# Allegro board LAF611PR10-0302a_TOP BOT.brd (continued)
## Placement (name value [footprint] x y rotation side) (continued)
CV212  0.1U_0201_6.3V6K  [C_0201]  207.16 91.02 90 bottom
CV213  4.7U_0603_6.3V6K  [C_0603]  232.72 100.22 0 top
CV214  1U_0402_6.3V6K  [C_0402]  226.76 100.01 270 top
CV373  10U_0603_6.3V6M  [C_0603]  223 149.51 90 top
CV374  1U_0402_6.3V6K  [C_0402]  235.13 144.44 270 top
CV375  1U_0402_6.3V6K  [C_0402]  237.48 148.13 270 top
CV376  1U_0402_6.3V6K  [C_0402]  237.92 140.19 270 bottom
CV377  1U_0402_6.3V6K  [C_0402]  237.92 141.97 270 bottom
CV378  1U_0402_6.3V6K  [C_0402]  237.92 146.48 270 bottom
CV379  1U_0402_6.3V6K  [C_0402]  237.92 148.32 270 bottom
CV380  1U_0402_6.3V6K  [C_0402]  231.19 146.96 90 top
CV381  10U_0603_6.3V6M  [C_0603]  202.46 149.57 90 top
CV382  1U_0402_6.3V6K  [C_0402]  204.87 144.63 270 top
CV383  1U_0402_6.3V6K  [C_0402]  208.81 146.92 270 top
CV384  1U_0402_6.3V6K  [C_0402]  217.26 142.73 270 bottom
CV385  1U_0402_6.3V6K  [C_0402]  201.95 147.97 90 bottom
CV386  1U_0402_6.3V6K  [C_0402]  217.26 145.71 270 bottom
CV387  1U_0402_6.3V6K  [C_0402]  208.75 149.18 90 top
CV388  1U_0402_6.3V6K  [C_0402]  210.65 149.12 90 top
CV389  10U_0603_6.3V6M  [C_0603]  261.78 91.99 0 top
CV390  1U_0402_6.3V6K  [C_0402]  259.92 92.12 0 top
CV391  1U_0402_6.3V6K  [C_0402]  261.13 100.69 0 top
CV392  1U_0402_6.3V6K  [C_0402]  258.87 98.97 180 top
CV393  1U_0402_6.3V6K  [C_0402]  261.13 98.97 0 top
CV394  1U_0402_6.3V6K  [C_0402]  263.8 96.18 0 top
CV395  1U_0402_6.3V6K  [C_0402]  263.8 104.12 0 top
CV396  1U_0402_6.3V6K  [C_0402]  252.01 107.42 180 bottom
CV397  10U_0603_6.3V6M  [C_0603]  261.14 127.6 0 top
CV398  1U_0402_6.3V6K  [C_0402]  261.13 121.13 0 top
CV399  1U_0402_6.3V6K  [C_0402]  263.54 123.41 0 top
CV400  1U_0402_6.3V6K  [C_0402]  261.19 119.41 0 top
CV401  1U_0402_6.3V6K  [C_0402]  258.11 127.92 180 bottom
CV402  1U_0402_6.3V6K  [C_0402]  251.89 128.05 180 bottom
CV403  1U_0402_6.3V6K  [C_0402]  263.54 117.44 0 top
CV404  1U_0402_6.3V6K  [C_0402]  259.86 113 0 top
CV529  0.1U_0201_6.3V6K  [C_0201]  212.27 89.36 0 bottom
CV530  0.1U_0201_6.3V6K  [C_0201]  231.02 86.83 180 bottom
CV531  0.22U_0201_6.3V6M  [C_0201]  202.99 102.4 180 top
CV532  0.22U_0201_6.3V6M  [C_0201]  202.99 101.7 180 top
CV533  0.22U_0201_6.3V6M  [C_0201]  201.53 102.71 180 top
CV534  0.22U_0201_6.3V6M  [C_0201]  201.53 103.28 180 top
CV535  0.22U_0201_6.3V6M  [C_0201]  202.99 104.17 180 top
CV536  0.22U_0201_6.3V6M  [C_0201]  202.99 103.6 180 top
CV537  0.22U_0201_6.3V6M  [C_0201]  201.53 104.49 180 top
CV538  0.22U_0201_6.3V6M  [C_0201]  201.53 105.06 180 top
CV539  0.22U_0201_6.3V6M  [C_0201]  202.99 105.95 180 top
CV540  0.22U_0201_6.3V6M  [C_0201]  202.99 105.38 180 top
CV541  0.22U_0201_6.3V6M  [C_0201]  201.53 106.27 180 top
CV542  0.22U_0201_6.3V6M  [C_0201]  201.53 106.84 180 top
CV543  0.22U_0201_6.3V6M  [C_0201]  202.99 107.73 180 top
CV544  0.22U_0201_6.3V6M  [C_0201]  202.99 107.16 180 top
CV545  0.22U_0201_6.3V6M  [C_0201]  201.53 108.05 180 top
CV546  0.22U_0201_6.3V6M  [C_0201]  201.53 108.62 180 top
CV597  10U_0603_6.3V6M  [C_0603]  15.37 100.21 90 top
CV598  0.1U_0402_10V6K  [C_0402]  16.56 100.13 90 top
CV599  0.1U_0402_25V6  [C_0402]  16.1 103.14 180 bottom
CV600  0.1U_0402_25V6  [C_0402]  16.1 100.66 180 bottom
CV601  0.1U_0402_25V6  [C_0402]  19.25 100.66 0 bottom
CV833  0.1U_0402_10V7K  [C_0402]  205.77 113.82 270 top
CV834  22U_0603_6.3V6M  [C_0603]  203.85 119.04 90 top
CV835  1U_0402_6.3V6K  [C_0402]  213.48 108.36 0 top
CV836  1U_0402_6.3V6K  [C_0402]  210.01 115.19 270 top
CV837  1U_0402_6.3V6K  [C_0402]  213.48 104.54 0 top
CV838  1U_0402_6.3V6K  [C_0402]  213.48 107.35 0 top
CV839  4.7U_0603_6.3V6K  [C_0603]  202.41 115.85 270 bottom
CV840  4.7U_0603_6.3V6K  [C_0603]  201.14 115.85 270 bottom
CV841  10U_0603_6.3V6M  [C_0603]  212.48 123.67 270 top
CV842  10U_0603_6.3V6M  [C_0603]  218.32 114.68 90 top
CV843  0.1U_0402_10V7K  [C_0402]  225.87 100.85 90 top
CV844  10U_0603_6.3V6M  [C_0603]  202.58 120.43 270 top
CV845  10U_0603_6.3V6M  [C_0603]  201.7 115.45 90 top
CV851  1U_0402_6.3V6K  [C_0402]  206.46 151.34 90 top
CV852  1U_0402_6.3V6K  [C_0402]  216.88 148.13 270 top
CV853  1U_0402_6.3V6K  [C_0402]  202.02 139.87 270 bottom
CV854  1U_0402_6.3V6K  [C_0402]  201.95 146.13 90 bottom
CV855  1U_0402_6.3V6K  [C_0402]  217.26 140.04 90 bottom
CV856  1U_0402_6.3V6K  [C_0402]  217.83 148.13 270 top
CV857  1U_0402_6.3V6K  [C_0402]  217.26 148.13 270 bottom
CV858  1U_0402_6.3V6K  [C_0402]  212.06 151.22 90 top
CV859  22U_0603_6.3V6M  [C_0603]  237.6 146.21 270 top
CV860  22U_0603_6.3V6M  [C_0603]  223 142.21 270 top
CV861  22U_0603_6.3V6M  [C_0603]  237.6 149.51 90 top
CV862  22U_0603_6.3V6M  [C_0603]  218.65 149.64 90 bottom
CV863  22U_0603_6.3V6M  [C_0603]  230.36 151.1 90 top
CV864  22U_0603_6.3V6M  [C_0603]  216.94 142.27 270 top
CV865  22U_0603_6.3V6M  [C_0603]  202.4 146.08 270 top
CV866  22U_0603_6.3V6M  [C_0603]  201.95 142.21 270 bottom
CV867  22U_0603_6.3V6M  [C_0603]  202.4 142.15 270 top
CV868  22U_0603_6.3V6M  [C_0603]  217 149.38 90 top
CV869  1U_0402_6.3V6K  [C_0402]  223.12 148.19 270 top
CV870  1U_0402_6.3V6K  [C_0402]  229.41 146.92 270 top
CV871  1U_0402_6.3V6K  [C_0402]  222.55 148.32 270 bottom
CV872  1U_0402_6.3V6K  [C_0402]  222.55 146.35 270 bottom
CV873  1U_0402_6.3V6K  [C_0402]  222.55 141.94 90 bottom
CV874  1U_0402_6.3V6K  [C_0402]  222.55 140.1 90 bottom
CV875  1U_0402_6.3V6K  [C_0402]  231.19 149.18 90 top
CV876  1U_0402_6.3V6K  [C_0402]  229.47 149.18 90 top
CV877  1U_0402_6.3V6K  [C_0402]  251.92 112.68 0 bottom
CV878  1U_0402_6.3V6K  [C_0402]  247.43 124.38 270 bottom
CV879  1U_0402_6.3V6K  [C_0402]  259.94 127.4 90 top
CV880  1U_0402_6.3V6K  [C_0402]  254.15 112.68 0 bottom
CV881  1U_0402_6.3V6K  [C_0402]  259.76 112.68 180 bottom
CV882  1U_0402_6.3V6K  [C_0402]  247.36 117.14 270 bottom
CV883  1U_0402_6.3V6K  [C_0402]  263.54 121.89 0 top
CV884  1U_0402_6.3V6K  [C_0402]  261.6 112.68 180 bottom
CV885  22U_0603_6.3V6M  [C_0603]  261.52 107.55 0 bottom
CV886  22U_0603_6.3V6M  [C_0603]  254.35 107.55 180 bottom
CV887  22U_0603_6.3V6M  [C_0603]  249.21 92.05 180 bottom
CV888  22U_0603_6.3V6M  [C_0603]  253.4 92.05 180 bottom
CV889  22U_0603_6.3V6M  [C_0603]  261.91 92.05 0 bottom
CV890  22U_0603_6.3V6M  [C_0603]  262.54 112.55 0 bottom
CV891  22U_0603_6.3V6M  [C_0603]  250.67 112.55 180 bottom
CV892  22U_0603_6.3V6M  [C_0603]  257.84 112.55 180 bottom
CV893  22U_0603_6.3V6M  [C_0603]  254.22 128.05 180 bottom
CV894  22U_0603_6.3V6M  [C_0603]  260.89 128.05 0 bottom
CV895  1U_0402_6.3V6K  [C_0402]  257.98 107.42 180 bottom
CV896  1U_0402_6.3V6K  [C_0402]  260.01 107.42 180 bottom
CV897  1U_0402_6.3V6K  [C_0402]  254.53 92.18 0 bottom
CV898  1U_0402_6.3V6K  [C_0402]  247.43 103.88 270 bottom
CV899  1U_0402_6.3V6K  [C_0402]  250.15 92.05 0 bottom
CV900  1U_0402_6.3V6K  [C_0402]  260.03 91.27 180 bottom
CV901  1U_0402_6.3V6K  [C_0402]  260.04 92.21 0 bottom
CV902  1U_0402_6.3V6K  [C_0402]  247.43 95.66 90 bottom
CV903  0.01U_0402_16V7K  [C_0402]  235.12 133.73 270 bottom
CV904  0.01U_0402_16V7K  [C_0402]  208.89 130.37 270 bottom
CV905  0.01U_0402_16V7K  [C_0402]  241.68 94.92 90 bottom
CV906  0.01U_0402_16V7K  [C_0402]  243.1 118.65 180 bottom
CV937  0.1U_0402_10V7K  [C_0402]  227.71 108.42 0 top
CV938  0.1U_0402_10V7K  [C_0402]  224.84 119.25 90 top
CV939  0.1U_0402_10V7K  [C_0402]  227.02 115.35 270 top
CV940  0.1U_0402_10V7K  [C_0402]  209.77 101.87 90 top
CV941  22U_0603_6.3V6M  [C_0603]  227.64 111.25 180 top
CV942  22U_0603_6.3V6M  [C_0603]  227.46 102.78 180 top
CV943  10U_0603_6.3V6M  [C_0603]  229.56 113.55 180 top
CV944  10U_0603_6.3V6M  [C_0603]  225.9 109.49 0 top
CV945  22U_0603_6.3V6M  [C_0603]  221.18 116.04 270 top
CV946  22U_0603_6.3V6M  [C_0603]  227.4 105.56 180 top
CV947  22U_0603_6.3V6M  [C_0603]  202.97 116.85 270 top
CW1  .1U_0402_16V7K  [C_0402]  39.29 95.1 90 bottom
CW2  .1U_0402_16V7K  [C_0402]  38.41 95.1 90 bottom
CW3  .1U_0402_16V7K  [C_0402]  25.08 108.18 180 top
CW4  .1U_0402_16V7K  [C_0402]  25.08 109.14 180 top
CW5  10U_0603_6.3V6M  [C_0603]  25.16 107.01 180 top
CW6  10U_0603_6.3V6M  [C_0603]  30.01 107.5 0 top
CW7  .1U_0402_16V7K  [C_0402]  30.25 106.36 0 top
CW8  .1U_0402_16V7K  [C_0402]  46.46 106.63 180 top
CW9  10P_0402_50V8J  [C_0402]  46.46 107.58 180 top
CX2  0.1U_0402_16V7K  [C_0402]  15.19 104.09 0 bottom
CZ9  0.1U_0402_10V7K  [C_0402]  58.72 30.75 0 top
CZ10  470P_0402_50V7K  [C_0402]  57.81 27.84 0 top
CZ11  0.01U_0402_16V7K  [C_0402]  57.81 28.73 0 top
CZ12  0.1U_0402_10V7K  [C_0402]  57.05 25.68 270 top
CZ23  1U_0603_10V6K  [C_0603]  52.83 26.66 270 top
CZ25  1U_0603_10V6K  [C_0603]  54.24 30.86 0 top
CZ28  0.1U_0402_10V6K  [C_0402]  116 122.9 0 bottom
CZ32  0.1U_0402_10V7K  [C_0402]  174.3 39.6 90 top
CZ33  100P_0402_50V8J  [C_0402]  175.34 35.68 0 top
CZ37  1U_0402_6.3V6K  [C_0402]  173.33 39.52 90 top
CZ40  0.1U_0402_10V7K  [C_0402]  173.6 35.68 0 top
CZ46  0.1U_0402_16V7K  [C_0402]  170.89 37.95 0 top
CZ47  0.1U_0402_10V6K  [C_0402]  106.03 118.68 0 bottom
CZ49  0.1U_0402_10V7K  [C_0402]  99.72 93.88 270 top
CZ50  0.1U_0402_10V7K  [C_0402]  98.94 87.61 270 top
CZ51  0.1U_0402_10V7K  [C_0402]  100.67 87.65 270 top
CZ57  2200P_0402_25V7K  [C_0402]  101.5 93.04 180 top
CZ86  0.1U_0402_10V7K  [C_0402]  112.47 119.57 0 bottom
CZ88  1U_0402_6.3V6K  [C_0402]  113.49 120.54 90 bottom
CZ96  1U_0402_6.3V6K  [C_0402]  115.74 117.88 270 bottom
CZ97  0.1U_0402_25V6  [C_0402]  114.79 117.88 270 bottom
CZ102  0.1U_0402_10V6K  [C_0402]  114.72 116.08 0 bottom
CZ108  0.22U_0402_10V4Z  [C_0402]  53.42 33.86 0 top
CZ109  10U_0603_6.3V6M  [C_0603]  58.13 25.73 0 top
CZ110  10U_0603_6.3V6M  [C_0603]  58.47 31.79 0 top
CZ111  0.1U_0402_10V6K  [C_0402]  111.27 117.44 0 bottom
D1  -  [BAS40C_SOT23-3]  179.55 27.63 0 bottom
D3  -  [BAT54CW_SOT323-3]  250.74 44.28 90 top
D4  -  [BAT54CW_SOT323-3]  254.34 46.86 270 top
D5  -  [RB551V-30_SOD323-2]  252.37 40.6 270 top
D6  -  [RB551V-30_SOD323-2]  236.65 38.12 270 bottom
D7  RB751S40T1G_SOD523-2  [RB520SM-30T2R_EMD2-2]  167.51 25.61 0 top
DA1  -  [L03ESDL5V0CC3-2_SOT23-3]  12.98 2.34 0 top
DA2  -  [L03ESDL5V0CC3-2_SOT23-3]  16.85 2.34 0 top
DA3  -  [BAT54CW_SOT323-3]  31.79 24.64 180 top
DA4  -  [L03ESDL5V0CC3-2_SOT23-3]  16.73 20.38 180 top
DA5  AZ5123-02S.R7G_SOT23-3  [AZ5123-02SPR7G_SOT23-3]  17.3 7.42 0 top
DA6  -  [AZC199-02SPR7G_SOT23-3]  260.43 38.91 90 top
DA7  -  [L03ESDL5V0CC3-2_SOT23-3]  20.59 21.81 180 top
DA8  BAT54ATB_SOT-523-3  [BAT54ATB_SOT523-3]  23.94 12.55 90 top
DC1  -  [L03ESDL5V0CC3-2_SOT23-3]  31.52 38.05 90 bottom
DC2  RB751S40T1G_SOD523-2  [RB520SM-30T2R_EMD2-2]  96.72 26.86 180 top
DE1  AZ5125-01H.R7G_SOD523-2  [AZ5125-01HPR7G_SOD523-2]  92.49 26.88 0 top
DE7  -  [RB751S40T1G_SOD523-2]  119.71 60.01 0 bottom
DE9  -  [RB751S40T1G_SOD523-2]  279.78 58.43 270 top
DF1  -  [AZC199-02SPR7G_SOT23-3]  239.52 36.78 90 bottom
DG3  -  [RB751S40T1G_SOD523-2]  201.04 87.2 180 bottom
DG4  -  [RB751S40T1G_SOD523-2]  238.56 90.92 0 bottom
DG7  -  [RB751S40T1G_SOD523-2]  197.73 93.8 90 bottom
DG10  -  [RB751S40T1G_SOD523-2]  198.16 87.1 90 bottom
DH1  -  [RB751V40_SC76-2]  195.66 34.45 180 bottom
DH2  -  [RB751S40T1G_SOD523-2]  189.65 40.99 180 top
DN1  -  [RB751S40T1G_SOD523-2]  37.87 101.29 0 top
DN2  -  [RB751S40T1G_SOD523-2]  37.87 102.5 0 top
DT2  AZ5B75-01B.R7G_CSP0603P2Y2  [ESD101-B1-02ELS_TSSLP-2-4-2]  9.92 117.53 270 bottom
DT3  AZ5B75-01B.R7G_CSP0603P2Y2  [ESD101-B1-02ELS_TSSLP-2-4-2]  9.92 118.24 90 bottom
DT4  AZ5B75-01B.R7G_CSP0603P2Y2  [ESD101-B1-02ELS_TSSLP-2-4-2]  13.44 118.12 270 top
DT5  AZ5B75-01B.R7G_CSP0603P2Y2  [ESD101-B1-02ELS_TSSLP-2-4-2]  13.44 118.83 90 top
DT6  AZ5B75-01B.R7G_CSP0603P2Y2  [ESD101-B1-02ELS_TSSLP-2-4-2]  11.84 125.01 90 top
DT7  AZ5B75-01B.R7G_CSP0603P2Y2  [ESD101-B1-02ELS_TSSLP-2-4-2]  11.84 124.29 270 top
DT8  AZ5B75-01B.R7G_CSP0603P2Y2  [ESD101-B1-02ELS_TSSLP-2-4-2]  11.84 125.01 90 bottom
DT9  AZ5B75-01B.R7G_CSP0603P2Y2  [ESD101-B1-02ELS_TSSLP-2-4-2]  11.84 124.29 270 bottom
DT10  -  [TVWDF1004AD0_DFN9]  11.89 120.49 90 top
DT11  -  [TVWDF1004AD0_DFN9]  13.4 107.22 180 bottom
DT16  AZ4024-02S_SOT23-3~D  [PESD24VS2UT_SOT23-3]  15.42 111.58 90 top
DT19  -  [RB551V-30_SOD323-2]  67.41 46.44 270 top
DT20  -  [RB551V-30_SOD323-2]  69.06 46.44 270 top
DT21  -  [RB551V-30_SOD323-2]  65.76 46.44 270 top
DU1  -  [L05ESDL5V0NA-4_SLP2510P8-10-9]  18.13 49.93 180 top
DU2  -  [AZC199-02SPR7G_SOT23-3]  19.55 50.01 0 bottom
DU3  -  [L05ESDL5V0NA-4_SLP2510P8-10-9]  23.99 26.21 270 top
DU4  -  [AZC199-02SPR7G_SOT23-3]  18.29 31.78 270 top
DV9  -  [RB751S40T1G_SOD523-2]  225.88 86.82 90 bottom
DV11  -  [RB751S40T1G_SOD523-2]  221.53 90.77 90 bottom
DZ1  -  [RB751S40T1G_SOD523-2]  114.3 114.95 0 bottom
DZ2  -  [RB751S40T1G_SOD523-2]  51.4 32.08 0 top
F1  1.5A_24V_SMD1812P150TF-24  [F_SMD1812P150TF-24]  266.47 61.9 180 bottom
F3  0.5A_13.2V_MF-NSMF050-2  [F_MF-NSMF050-2]  157.99 45.58 0 bottom
FD1  FIDUCAL  [FIDUCIAL_C40M80]  32.82 143.52 0 top
FD2  FIDUCAL  [FIDUCIAL_C40M80]  271.95 27.34 0 top
FD3  FIDUCAL  [FIDUCIAL_C40M80]  249.78 145.03 0 top
FD4  FIDUCAL  [FIDUCIAL_C40M80]  249.78 145.03 180 bottom
FD5  FIDUCAL  [FIDUCIAL_C40M80]  37.31 4.42 180 bottom
H1  HOLEA  [H_3P7-G]  6.85 130.5 0 top
H2  HOLEA  [H_3P3]  6.9 112.6 0 top
H3  HOLEA  [H_5P6N]  19.1 107.3 0 top
H4  HOLEA  [H_3P0]  7.9 85.8 0 top
H5  HOLEA  [H_3P2]  37.7 132.45 0 top
H6  HOLEA  [H_4P0]  183.7 70.5 0 top
H7  HOLEA  [H_3P0X3P3]  30.25 4.5 0 top
H8  HOLEA  [H_4P0-G]  196.45 42 0 top
H9  HOLEA  [H_4P0-G]  93.7 153 0 top
H10  HOLEA  [H_4P0-G]  9.8 41.2 0 top
H11  HOLEA  [H_4P0]  246.7 153 0 top
H12  HOLEA  [H_2P3]  191.1 152.3 0 top
H13  HOLEA  [H_4P0]  120.85 28.1 0 top
H14  HOLEA  [H_3P5X3P0N]  253.07 148.17 0 top
H15  HOLEA  [H_7P0]  280.8 25.92 0 top
H16  HOLEA  [H_4P0]  280.85 48.25 0 top
HCPU1  HOLEA  [H_3P7]  53 126.25 0 top
HCPU2  HOLEA  [H_3P7]  111.8 126.25 0 top
HCPU3  HOLEA  [H_3P7]  53 103.65 0 top
HCPU4  HOLEA  [H_3P7]  111.8 103.65 0 top
HGPU2  HOLEA  [H_3P7]  192.86 86.5 0 top
HGPU3  HOLEA  [H_3P7]  194.2 133.05 0 top
HGPU4  HOLEA  [H_3P7]  248.2 80.5 0 top
JDEG1  JXT_FP241AH-010GAAM  [JXT_FP241AH-010GAAM_10P]  65.46 29.09 0 top
JDIMM1  DEREN_40-42271-26001RHF  [LOTES_ADDR0206-P001A02_260P]  44.32 71.05 180 bottom
JDIMM2  DEREN_40-42261-26001RHF  [LOTES_ADDR0205-P001A02_260P]  47.33 58.3 0 bottom
JEDP1  ACES_51540-04001-P01  [ACES_51540-04001-P01_40P]  255.23 56.65 270 bottom
JESPI1  JXT_FP241AH-010GAAM  [JXT_FP241AH-010GAAM_10P-NPM]  75.15 44.1 270 bottom
JFAN1  ACES_50224-00401-001  [ACES_50224-00401-001_4P]  119.25 68.11 0 bottom
JFAN2  ACES_50224-00401-001  [ACES_50224-00401-001_4P]  276.2 59.42 0 bottom
JFP  ACES_51522-00801-001  [ACES_51522-00801-001_8P]  246.35 33.2 180 bottom
JHDD  ACES_51625-01201-001  [ACES_51625-01201-001_12P]  273.3 41.75 270 bottom
JHDMI1  ACON_HMRBL-AK120D  [ACON_HMRBL-AK120D_19P]  11.05 92.35 90 bottom
JHP1  SINGA_2SJ3095-136111F~D  [SINGA_2SJ3095-136111F_6P]  12.7 7.9 270 bottom
JIOB1  TWVM_FPC1020-18RC-TA0HC  [TWVM_FPC1020-18RC-TA0HC_18P]  255 33.17 180 bottom
JKB  ACES_51698-03001-001  [ACES_51698-03001-001_30P-T]  128.4 34.95 180 bottom
JKBBL  ACES_51575-00401-001  [ACES_51575-00401-001_4P]  158.2 43.52 180 bottom
JLAN1  SINGA_2RJ3076-058211F  [SINGA_2RJ3076-058211F_8P]  12.95 77.72 90 bottom
JP5  -  [JUMP_43X79]  272.82 35.65 0 top
JP10  -  [JUMP_43X79]  45.3 29.06 0 top
JSPK1  ACES_50224-00401-001  [ACES_50224-00401-001_4P]  15.9 5.83 180 bottom
JSSD1  LCN_DAN05-67306-0103  [LCN_DAN05-67306-0103_75P]  39.37 34.02 180 bottom
JTP  ACES_51524-0080N-001  [ACES_51524-0080N-001_8P]  234.55 32.95 180 bottom
JUSB1  LOTES_AUSB0172-P001A  [LOTES_AUSB0172-P001A_9P]  15.88 56.65 90 bottom
JUSB2  LOTES_AUSB0172-P001A  [LOTES_AUSB0172-P001A_9P]  15.88 32.75 90 bottom
JUSBC1  FOX_UT12113-116B2-7H  [FOX_UT12113-116B2-7H_24P]  7.35 123.82 270 top
JWLAN1  LOTES_APCI0136-P001A  [LOTES_APCI0136-P001A_75P]  28.45 98.92 0 bottom
L3  MCM1012B900F06BP_4P  [INPAQ_MCM1012B900F06BP_4P]  252.5 40.14 0 bottom
L4  MCM1012B900F06BP_4P  [INPAQ_MCM1012B900F06BP_4P-NPM]  259.85 42.74 270 top
L5  BLM15PX221SN1D_2P  [MURAT_BLM15PX221SN1D_2P]  37.66 13.73 180 top
LA1  BLM15PX330SN1D_2P  [MURAT_BLM15PX330SN1D_2P]  16.84 12.19 270 top
LA2  BLM15PX330SN1D_2P  [MURAT_BLM15PX330SN1D_2P]  15.7 15.64 90 top
LA3  BLM15PX330SN1D_2P  [MURAT_BLM15PX330SN1D_2P]  17.96 15.65 90 top
LA4  BLM15PX330SN1D_2P  [MURAT_BLM15PX330SN1D_2P]  17.81 12.18 270 top
LED1  LTW-295DSKS-5A_YEL-WHITE~D  [LED_LTW-295DSKS-5A_4P]  3.55 135.55 270 bottom
LG8  PBY160808T-300Y-N_2P  [CHILI_PBY160808T-300Y-N_2P]  213.88 103.05 270 top
LT1  0.6UH_MND-04ABIR60M-XGL_20%  [MAG_MND-04ABIR60M-XGL_2P]  16.56 134.19 180 bottom
LT2  MCM1012B900F06BP_4P  [INPAQ_MCM1012B900F06BP_4P]  14.46 120.47 180 top
LT3  MCM1012B900F06BP_4P  [INPAQ_MCM1012B900F06BP_4P]  14.46 122 180 top
LT4  1UH_LQM18PN1R0MFHD_20%  [MURAT_LQM18PN1R0MFHD_2P]  31.7 121.54 0 bottom
LU1  MCM1012B900F06BP_4P  [INPAQ_MCM1012B900F06BP_4P]  20.53 45.81 270 bottom
LU2  HCM1012GH900BP_4P  [INPAQ_HCM1012GH900BP_4P]  20.14 48.27 270 top
LU3  HCM1012GH900BP_4P  [INPAQ_HCM1012GH900BP_4P]  18.45 48.27 270 top
LU4  MCM1012B900F06BP_4P  [INPAQ_MCM1012B900F06BP_4P]  23.11 30.41 0 top
LU5  HCM1012GH900BP_4P  [INPAQ_HCM1012GH900BP_4P]  25.63 28.2 0 top
LU6  HCM1012GH900BP_4P  [INPAQ_HCM1012GH900BP_4P]  25.72 26.58 0 top
LU8  MCM1012B900F06BP_4P  [INPAQ_MCM1012B900F06BP_4P]  257.24 35.09 90 top
LU9  MCM1012B900F06BP_4P  [INPAQ_MCM1012B900F06BP_4P]  260.23 35.08 90 top
LV3  HCM1012GH900BP_4P  [INPAQ_HCM1012GH900BP_4P-NPM]  17.83 95.91 180 top
LV4  HCM1012GH900BP_4P  [INPAQ_HCM1012GH900BP_4P-NPM]  18.67 97.97 180 top
LV5  HCM1012GH900BP_4P  [INPAQ_HCM1012GH900BP_4P-NPM]  18.44 93.04 180 top
LV6  HCM1012GH900BP_4P  [INPAQ_HCM1012GH900BP_4P-NPM]  18.44 90.75 180 top
LV7  BLM15AX300SN1D  [C_0402]  205.11 98.76 270 top
LV13  BLM15AX300SN1D  [C_0402]  207.85 114.32 90 top
NOREF  -  []  37.7 132.45 0 top
NOREF#2  -  []  191.1 152.3 0 top
NOREF#3  -  []  120.85 28.1 0 top
NOREF#4  -  []  59.5 78.23 0 top
NOREF#5  -  []  124.84 -37.54 0 top
NOREF#6  -  []  93.14 78.23 0 top
NOREF#7  -  []  49.31 85.13 0 top
NOREF#8  -  []  53 103.65 270 top
NOREF#9  -  []  7.9 85.8 0 top
NOREF#10  -  []  53 126.25 270 top
NOREF#11  -  []  280.8 25.92 0 top
NOREF#12  -  []  75.93 79.49 90 top
NOREF#13  -  []  194.2 133.05 270 top
NOREF#14  -  []  7.9 85.8 0 top
NOREF#15  -  []  183.7 70.5 0 top
NOREF#16  -  []  111.8 126.25 270 top
NOREF#17  -  []  196.45 42 0 top
NOREF#18  -  []  105.19 80.07 0 top
NOREF#19  -  []  192.86 86.5 0 top
NOREF#20  -  []  33.1 75.38 0 top
NOREF#21  -  []  108.37 70.47 0 top
NOREF#22  -  []  111.8 103.65 270 top
NOREF#23  -  []  245.8 133.05 0 top
NOREF#24  -  []  280.85 48.25 0 top
NOREF#25  -  []  248.2 80.5 0 top
NOREF#26  -  []  30.25 4.5 0 top
NOREF#27  -  []  107.12 75.84 180 bottom
NOREF#28  -  []  93.7 153 180 bottom
NOREF#29  -  []  246.7 153 180 bottom
NOREF#30  -  []  102.06 86.19 180 bottom
NOREF#31  -  []  238.12 131.66 180 bottom
NOREF#32  -  []  173.13 103.96 180 bottom
PBATT1  -  [ACES_50458-01001-P01_10P-T]  218.9 36.84 180 bottom
PC1  1000P_0402_50V7K  [C_0402]  43.37 134 180 bottom
PC2  330P_0402_50V7K  [C_0402]  43.37 134.93 180 bottom
PC3  1000P_0402_50V7K  [C_0402]  43.38 132.82 180 bottom
PC4  330P_0402_50V7K  [C_0402]  43.38 131.92 180 bottom
PC5  0.022U_0603_50V7K  [C_0603]  37.68 118.31 180 top
PC6  0.022U_0603_50V7K  [C_0603]  36.5 107.34 270 top
PC7  0.1U_0402_50V7K  [C_0402]  34.43 118.05 90 top
PC8  1000P_0603_50V7K  [C_0603]  37.92 117.35 0 bottom
PC9  2.2U_0402_10V6M  [C_0402]  41.22 117.49 180 bottom
PC10  0.1U_0402_50V7K  [C_0402]  30.93 109.69 270 top
PC11  0.01U_0402_25V7K  [C_0402]  218.19 46.38 180 bottom
PC12  1000P_0402_50V7K  [C_0402]  214.91 42.34 180 bottom
PC13  .1U_0402_16V7K  [C_0402]  45.51 123.54 0 bottom
PC14  .1U_0402_16V7K  [C_0402]  272.92 59.28 270 top
PC22  0.1U_0402_10V7K  [C_0402]  32.95 114.78 90 bottom
PC23  0.1U_0402_10V7K  [C_0402]  33.48 108.87 180 top
PC24  .1U_0402_16V7K  [C_0402]  44.6 123.6 270 bottom
PC301  1000P_0402_25V8J  [C_0402]  214.07 52.02 0 bottom
PC302  2200P_0402_50V7K  [C_0402]  214.15 51.07 0 bottom
PC303  4.7U_0805_25V6K  [C_0805]  213.28 53.41 0 bottom
PC304  4.7U_0805_25V6K  [C_0805]  212.87 50.6 270 top
PC305  0.1U_0402_25V6  [C_0402]  214.11 51.99 0 top
PC306  1000P_0402_25V8J  [C_0402]  214.15 51.07 0 top
PC307  0.1U_0402_10V7K  [C_0402]  208.99 53.85 270 bottom
PC308  4.7U_0603_6.3V6M  [C_0603]  209.2 46.91 270 bottom
PC309  680P_0603_50V7K  [C_0603]  201.93 54.27 90 top
PC310  22U_0805_6.3V6M  [C_0805]  200.39 48.67 180 top
PC311  22U_0805_6.3V6M  [C_0805]  200.39 48.67 180 bottom
PC312  22U_0805_6.3V6M  [C_0805]  201.59 48.63 0 top
PC313  22U_0805_6.3V6M  [C_0805]  201.46 52.13 0 top
PC314  22U_0805_6.3V6M  [C_0805]  201.51 50.38 0 top
PC315  1000P_0402_25V8J  [C_0402]  211.19 46.19 270 bottom
PC501  1000P_0402_25V8J  [C_0402]  124.21 57.67 90 top
PC502  2200P_0402_50V7K  [C_0402]  124.21 57.67 90 bottom
PC503  10U_0805_25V6K  [C_0805]  121.98 56.73 90 bottom
PC504  10U_0805_25V6K  [C_0805]  121.98 56.73 90 top
PC505  0.1U_0402_25V6  [C_0402]  123.28 57.67 90 bottom
PC506  1000P_0402_25V8J  [C_0402]  123.28 57.67 90 top
PC507  0.1U_0402_10V7K  [C_0402]  119.67 51.78 0 bottom
PC508  4.7U_0603_6.3V6M  [C_0603]  130.39 51.64 0 bottom
PC509  680P_0603_50V7K  [C_0603]  121.98 45.7 180 top
PC510  22U_0805_6.3V6M  [C_0805]  130.71 44.22 0 bottom
PC511  22U_0805_6.3V6M  [C_0805]  130.71 42.49 0 bottom
PC512  22U_0805_6.3V6M  [C_0805]  130.96 47.83 0 bottom
PC513  22U_0805_6.3V6M  [C_0805]  130.96 49.6 0 bottom
PC514  22U_0805_6.3V6M  [C_0805]  130.96 46 0 bottom
PC515  4.7U_0603_6.3V6M  [C_0603]  130.39 52.91 0 bottom
PC516  4.7U_0402_6.3V6M  [C_0402]  129.51 56.72 0 bottom
PC517  1000P_0402_25V8J  [C_0402]  129.48 54.15 0 bottom
PC518  22U_0805_6.3V6M  [C_0805]  129.24 42.58 270 bottom
PC901  1000P_0402_50V7K  [C_0402]  45 112.27 180 bottom
PC902  1000P_0402_50V7K  [C_0402]  45 111.38 180 bottom
PC903  2200P_0402_50V7K  [C_0402]  44.98 115.11 180 bottom
PC904  0.1U_0402_25V6  [C_0402]  44.98 116 180 bottom
PC905  10U_0805_25V6K  [C_0805]  45.9 113.69 180 top
PC906  10U_0805_25V6K  [C_0805]  45.92 113.69 180 bottom
PC907  0.1U_0603_25V7K  [C_0603]  50.18 112.47 90 bottom
PC908  0.22U_0402_10V6K  [C_0402]  46.65 118.41 0 top
PC909  1U_0603_6.3V6M  [C_0603]  50.15 119.94 90 bottom
PC910  2.2U_0402_16V6K  [C_0402]  46.5 117.5 270 top
PC911  680P_0603_50V7K  [C_0603]  55.39 120.19 0 bottom
PC912  330P_0402_50V7K  [C_0402]  49 120.94 270 bottom
PC913  22U_0603_6.3V6M  [C_0603]  55.25 115.11 0 bottom
PC914  22U_0603_6.3V6M  [C_0603]  55.25 116.38 0 bottom
PC915  22U_0603_6.3V6M  [C_0603]  55.26 118.86 0 bottom
PC916  22U_0603_6.3V6M  [C_0603]  55.26 117.63 0 bottom
PC1001  22U_0603_6.3V6M  [C_0603]  202.4 74.21 90 bottom
PC1002  1U_0603_6.3V6M  [C_0603]  201.12 75.61 270 bottom
PC1003  22P_0603_50V8  [C_0603]  208.51 75.38 180 bottom
PC1004  680P_0402_50V7K  [C_0402]  200.77 76.67 0 bottom
PC1005  22U_0603_6.3V6M  [C_0603]  199.72 84.7 90 bottom
PC1006  22U_0603_6.3V6M  [C_0603]  207.51 83.95 270 bottom
PC1007  22U_0603_6.3V6M  [C_0603]  200.99 84.7 90 bottom
PC1008  0.1U_0402_16V7K  [C_0402]  207.76 77.41 270 bottom
PC1801  22U_0603_6.3V6M  [C_0603]  196.89 67.11 180 bottom
PC1802  22U_0603_6.3V6M  [C_0603]  202.38 63.5 180 bottom
PC1803  22U_0603_6.3V6M  [C_0603]  202.38 63.5 180 top
PC1804  22U_0603_6.3V6M  [C_0603]  202.36 62.19 180 bottom
PC1805  0.1U_0402_10V7K  [C_0402]  200.81 65.56 180 bottom
PC1806  680P_0402_50V7K  [C_0402]  206.71 70.94 0 bottom
PC1807  22P_0402_50V8J  [C_0402]  196.34 65.12 0 bottom
PC2501  10U_0805_10V6K  [C_0805]  127.41 62.6 90 bottom
PC2502  10U_0805_10V6K  [C_0805]  117.83 63.58 270 bottom
PC2503  0.1U_0402_10V6K  [C_0402]  126.91 65.44 0 bottom
PC2504  1U_0402_6.3V6K  [C_0402]  124.89 60.15 180 bottom
PC2505  0.01U_0402_25V7K  [C_0402]  118.16 64.56 90 bottom
PCA01  2200P_0402_50V7K  [C_0402]  107.51 132.61 0 bottom
PCA02  0.1U_0402_25V7K  [C_0402]  107.51 131.71 0 bottom
PCA03  10U_0805_25VAK  [C_0805]  105.04 132.14 180 bottom
PCA04  10U_0805_25VAK  [C_0805]  105.04 132.14 180 top
PCA05  10U_0805_25VAK  [C_0805]  106.51 135.95 180 top
PCA06  10U_0805_25VAK  [C_0805]  106.51 134.23 180 top
PCA07  1U_0603_25V7K  [C_0603]  109.13 136.14 180 bottom
PCA08  2.2U_0603_10V7K  [C_0603]  109.15 138.6 270 bottom
PCA09  0.22U_0603_25V7K  [C_0603]  109.13 133.72 180 bottom
PCA10  2200P_0603_50V7K  [C_0603]  100.38 134.15 0 top
PCA11  1000P_0402_50V7K  [C_0402]  107.51 132.61 0 top
PCA12  1000P_0402_50V7K  [C_0402]  107.51 131.71 0 top
PCA101  47U_0805_6.3V6M  [C_0805]  95 114.59 0 top
PCA102  47U_0805_6.3V6M  [C_0805]  95 116.32 0 top
PCA103  47U_0805_6.3V6M  [C_0805]  95 118.06 0 top
PCA104  47U_0805_6.3V6M  [C_0805]  95 119.81 0 top
PCA105  22U_0603_6.3V6M  [C_0603]  98.9 131.9 0 top
PCA106  22U_0603_6.3V6M  [C_0603]  96.25 131.85 180 top
PCA107  10U_0402_6.3V6M  [C_0402]  96.2 133.86 180 top
PCA108  10U_0402_6.3V6M  [C_0402]  96.2 132.95 180 top
PCA109  10U_0402_6.3V6M  [C_0402]  98.52 133.86 0 top
PCA110  10U_0402_6.3V6M  [C_0402]  98.52 132.96 0 top
PCA111  10U_0402_6.3V6M  [C_0402]  95.1 111.97 0 top
PCA112  10U_0402_6.3V6M  [C_0402]  95.1 113.28 0 top
PCA113  10U_0402_6.3V6M  [C_0402]  95.48 110.71 0 top
PCB01  0.1U_0402_25V6  [C_0402]  245.16 37.66 180 top
PCB02  2200P_0402_50V7K  [C_0402]  245.16 37.67 180 bottom
PCB03  22U_0805_25V6M  [C_0805]  247.4 54.26 180 top
PCB04  22U_0805_25V6M  [C_0805]  245.21 36.2 180 top
PCB05  22U_0805_25V6M  [C_0805]  245.22 36.18 180 bottom
PCB06  22U_0805_25V6M  [C_0805]  247.4 54.27 180 bottom
PCB07  33U_D2_25VM_R40M  [C_EEFCX1E330R]  223.97 35.34 180 top
PCB10  10U_0805_25V6K~D  [C_0805]  226.59 43.93 180 top
PCB11  10U_0805_25V6K~D  [C_0805]  226.59 43.93 180 bottom
PCB12  10U_0805_25V6K~D  [C_0805]  222.65 51.87 90 bottom
PCB13  10U_0805_25V6K~D  [C_0805]  229.17 41.98 0 top
PCB14  10U_0805_25V6K~D  [C_0805]  229.17 40.21 0 top
PCB15  10U_0805_25V6K~D  [C_0805]  226.2 51.86 90 bottom
PCB16  10U_0805_25V6K~D  [C_0805]  222.66 51.87 90 top
PCB17  10U_0805_25V6K~D  [C_0805]  224.43 51.86 90 bottom
PCB18  4.7U_0402_6.3V6M  [C_0402]  268.38 49.22 180 top
PCB19  1U_0402_25V6K  [C_0402]  268.94 48.32 270 top
PCB20  1U_0402_25V6K  [C_0402]  267.13 48.3 270 top
PCB21  0.1U_0402_25V6  [C_0402]  220.37 52.2 90 bottom
PCB22  2200P_0402_50V7K  [C_0402]  221.26 52.2 90 top
PCB23  2200P_0402_50V7K  [C_0402]  220.37 52.2 90 top
PCB24  1000P_0402_50V7K  [C_0402]  221.26 52.2 90 bottom
PCB25  0.22U_0603_25V7K  [C_0603]  263.41 47.78 90 top
PCB26  0.1U_0402_25V6  [C_0402]  270.46 47.7 0 top
PCB27  1U_0603_25V6  [C_0603]  271.3 50.1 270 top
PCB28  1U_0402_6.3V6K  [C_0402]  270.51 51.54 0 top
PCB29  1U_0402_6.3V6K  [C_0402]  262.34 49.27 270 top
PCB30  0.22U_0603_25V7K  [C_0603]  260.96 52 180 top
PCB31  10U_0805_25V6K~D  [C_0805]  226.97 40.17 270 bottom
PCB32  10U_0805_25V6K~D  [C_0805]  225.2 40.17 270 bottom
PCB33  4700P_0402_25V7K  [C_0402]  223.8 37.41 0 bottom
PCB34  10P_0402_50V8J  [C_0402]  267.17 60.21 180 top
PCB35  0.1U_0402_25V6  [C_0402]  261.58 53.85 180 top
PCB36  680P_0603_50V7K  [C_0603]  243.33 43.05 180 top
PCB37  680P_0603_50V7K  [C_0603]  240.13 55.43 270 top
PCB38  1U_0402_25V6K  [C_0402]  262.81 54.74 90 top
PCB39  560P_0402_50V7K  [C_0402]  266.56 57.46 90 top
PCB40  0.1U_0402_25V6  [C_0402]  264.31 60.54 0 top
PCB41  1U_0402_25V6K  [C_0402]  261.87 54.73 90 top
PCB42  0.01UF_0402_25V7K  [C_0402]  267.14 59.25 180 top
PCB43  0.22U_0402_25V6K  [C_0402]  261.88 56.53 180 top
PCB44  0.1U_0402_10V7K  [C_0402]  39.27 36.72 180 top
PCB45  0.1U_0402_25V6  [C_0402]  263.11 58.27 180 top
PCB53  10U_0805_25V6K~D  [C_0805]  224.43 51.87 90 top
PCB54  10U_0805_25V6K~D  [C_0805]  226.2 51.87 90 top
PCB56  0.1U_0402_25V6  [C_0402]  269.25 45.12 180 top
PCB57  1000P_0402_25V8J  [C_0402]  241.72 50.7 180 top
PCG01  2200P_0402_50V7K  [C_0402]  61.87 151.78 90 bottom
PCG02  0.1U_0402_25V7K  [C_0402]  62.78 151.79 90 bottom
PCG03  10U_0805_25VAK  [C_0805]  62.13 148.75 270 bottom
PCG04  10U_0805_25VAK  [C_0805]  62.13 148.75 270 top
PCG05  10U_0805_25VAK  [C_0805]  58.71 150.17 270 top
PCG06  10U_0805_25VAK  [C_0805]  60.41 150.17 270 top
PCG07  1U_0603_25V7K  [C_0603]  58.15 152.78 270 bottom
PCG08  2.2U_0603_10V7K  [C_0603]  55.61 152.83 0 bottom
PCG09  0.22U_0603_25V7K  [C_0603]  60.59 152.78 270 bottom
PCG10  2200P_0603_50V7K  [C_0603]  59.57 143.76 90 top
PCG11  1000P_0402_50V7K  [C_0402]  61.87 151.78 90 top
PCG12  1000P_0402_50V7K  [C_0402]  62.78 151.79 90 top
PCG101  47U_0805_6.3V6M  [C_0805]  72.99 113.27 180 top
PCG102  47U_0805_6.3V6M  [C_0805]  72.98 116.84 180 top
PCG103  47U_0805_6.3V6M  [C_0805]  72.98 115.06 180 top
PCG104  22U_0603_6.3V6M  [C_0603]  74.38 114.62 0 top
PCG105  22U_0603_6.3V6M  [C_0603]  69.94 113.18 180 top
PCG106  22U_0603_6.3V6M  [C_0603]  69.94 114.45 180 top
PCG107  22U_0603_6.3V6M  [C_0603]  69.94 116.99 180 top
PCG108  22U_0603_6.3V6M  [C_0603]  69.94 115.72 180 top
PCG109  22U_0603_6.3V6M  [C_0603]  74.35 117.11 0 top
PCG110  22U_0603_6.3V6M  [C_0603]  74.35 115.89 0 top
PCG111  10U_0402_6.3V6M  [C_0402]  74.86 119.2 0 top
PCG112  10U_0402_6.3V6M  [C_0402]  74.86 118.28 0 top
PCG113  10U_0402_6.3V6M  [C_0402]  73.26 118.23 180 top
PCG114  10U_0402_6.3V6M  [C_0402]  73.28 119.15 180 top
PCG115  10U_0402_6.3V6M  [C_0402]  69.93 119.12 0 top
PCG116  10U_0402_6.3V6M  [C_0402]  69.93 118.2 0 top
PCG117  10U_0402_6.3V6M  [C_0402]  68.64 118.19 180 top
PCG118  10U_0402_6.3V6M  [C_0402]  68.65 119.11 180 top
PCG119  10U_0402_6.3V6M  [C_0402]  74.9 113.43 0 top
PCG120  10U_0402_6.3V6M  [C_0402]  74.88 112.49 0 top
PCG121  1U_0201_6.3V6M  [C_0201]  68.21 110.92 180 top
PCG122  1U_0201_6.3V6M  [C_0201]  68.18 111.48 180 top
PCG123  1U_0201_6.3V6M  [C_0201]  69.35 111.49 0 top
PCG124  1U_0201_6.3V6M  [C_0201]  75.02 111.53 180 top
PCG125  1U_0201_6.3V6M  [C_0201]  69.35 110.91 0 top
PCG126  1U_0201_6.3V6M  [C_0201]  75.9 111.5 0 top
PCG127  1U_0201_6.3V6M  [C_0201]  75.9 110.91 0 top
PCG128  1U_0201_6.3V6M  [C_0201]  75.03 110.88 180 top
PCG129  1U_0201_6.3V6M  [C_0201]  72.75 111.49 0 top
PCG130  1U_0201_6.3V6M  [C_0201]  72.75 110.91 0 top
PCG131  1U_0201_6.3V6M  [C_0201]  71.65 110.94 180 top
PCG132  1U_0201_6.3V6M  [C_0201]  71.65 111.54 180 top
PCG171  220U_D7_2VM_R6M  [C_EEFSS0D221R]  59.95 134.69 0 top
PCG172  220U_D7_2VM_R6M  [C_EEFSS0D221R]  60.08 134.43 180 bottom
PCH01  0.1U_0402_25V6  [C_0402]  133.71 52.53 180 bottom
PCH02  2200P_0402_50V7K  [C_0402]  133.71 51.64 180 bottom
PCH03  10U_0805_25V6K~D  [C_0805]  138.85 55.12 90 bottom
PCH04  10U_0805_25V6K~D  [C_0805]  137.08 55.11 90 bottom
PCH06  1000P_0402_50V7K  [C_0402]  133.73 54.4 180 bottom
PCH07  1000P_0402_50V7K  [C_0402]  133.73 53.48 180 bottom
PCH08  0.1U_0603_25V7K  [C_0603]  137.25 44.77 180 bottom
PCH09  0.1U_0402_16V7K  [C_0402]  136.08 38.81 270 bottom
PCH10  1U_0603_6.3V6M  [C_0603]  133.96 45.06 90 bottom
PCH12  680P_0402_50V7K  [C_0402]  139.91 41.68 0 bottom
PCH13  220U_D2 SX_2VY_R9M  [C_D2]  143.67 44.2 270 bottom
PCH14  220U_D2 SX_2VY_R9M  [C_D2]  148.36 44.17 270 bottom
PCI03  1000P_0402_50V7K  [C_0402]  95.46 145.58 90 top
PCI04  1000P_0402_50V7K  [C_0402]  96.37 145.58 90 top
PCI05  33U_D2_25VM_R40M  [C_EEFCX1E330R]  68.09 154.23 180 top
PCI06  33U_D2_25VM_R40M  [C_EEFCX1E330R]  84.65 154.23 0 top
PCI07  33U_D2_25VM_R40M  [C_EEFCX1E330R]  114.02 132.81 270 bottom
PCI08  2200P_0402_50V7K  [C_0402]  95.46 145.57 90 bottom
PCI09  0.1U_0402_25V7K  [C_0402]  96.37 145.58 90 bottom
PCI10  10U_0805_25VAK  [C_0805]  95.55 143.49 270 bottom
PCI11  10U_0805_25VAK  [C_0805]  95.55 143.49 270 top
PCI12  10U_0805_25VAK  [C_0805]  91.96 144.89 270 top
PCI13  10U_0805_25VAK  [C_0805]  93.68 144.89 270 top
PCI14  1U_0603_25V7K  [C_0603]  91.03 146.28 180 top
PCI15  2.2U_0603_10V7K  [C_0603]  88.23 147.48 0 bottom
PCI16  0.22U_0603_25V7K  [C_0603]  93.12 146.17 0 bottom
PCI17  2200P_0603_50V7K  [C_0603]  92.76 138.75 90 top
PCI18  2200P_0402_50V7K  [C_0402]  86.44 151.67 90 bottom
PCI19  0.1U_0402_25V7K  [C_0402]  87.35 151.68 90 bottom
PCI20  10U_0805_25VAK  [C_0805]  86.88 149.52 270 bottom
PCI21  10U_0805_25VAK  [C_0805]  87.03 149.52 270 top
PCI22  10U_0805_25VAK  [C_0805]  83.58 150.92 270 top
PCI23  10U_0805_25VAK  [C_0805]  85.29 150.92 270 top
PCI24  1U_0603_25V7K  [C_0603]  82.92 153.55 270 bottom
PCI25  2.2U_0603_10V7K  [C_0603]  80.38 153.59 0 bottom
PCI26  0.22U_0603_25V7K  [C_0603]  85.35 153.55 270 bottom
PCI27  2200P_0603_50V7K  [C_0603]  84.35 144.66 90 top
PCI28  2200P_0402_50V7K  [C_0402]  78.38 152.55 90 bottom
PCI29  0.1U_0402_25V7K  [C_0402]  79.29 152.55 90 bottom
PCI30  10U_0805_25VAK  [C_0805]  78.64 149.52 270 bottom
PCI31  10U_0805_25VAK  [C_0805]  78.63 149.51 270 top
PCI32  10U_0805_25VAK  [C_0805]  76.74 150.92 270 top
PCI33  10U_0805_25VAK  [C_0805]  74.97 150.92 270 top
PCI34  1U_0603_25V7K  [C_0603]  74.66 153.55 270 bottom
PCI35  2.2U_0603_10V7K  [C_0603]  72.15 153.55 0 bottom
PCI36  0.22U_0603_25V7K  [C_0603]  77.1 153.55 270 bottom
PCI37  2200P_0603_50V7K  [C_0603]  76.07 144.75 90 top
PCI38  2200P_0402_50V7K  [C_0402]  70.12 152.55 90 bottom
PCI39  0.1U_0402_25V7K  [C_0402]  71.03 152.55 90 bottom
PCI40  10U_0805_25VAK  [C_0805]  68.64 150.94 270 top
PCI41  10U_0805_25VAK  [C_0805]  66.94 150.94 270 top
PCI42  10U_0805_25VAK  [C_0805]  70.4 149.52 270 bottom
PCI43  10U_0805_25VAK  [C_0805]  70.38 149.52 270 top
PCI44  1U_0603_25V7K  [C_0603]  66.41 153.55 270 bottom
PCI45  2.2U_0603_10V7K  [C_0603]  63.87 153.58 0 bottom
PCI46  0.22U_0603_25V7K  [C_0603]  68.84 153.55 270 bottom
PCI47  2200P_0603_50V7K  [C_0603]  67.84 144.66 90 top
PCI48  1000P_0402_50V7K  [C_0402]  80.37 149.06 270 top
PCI49  1000P_0402_50V7K  [C_0402]  81.28 149.06 270 top
PCI50  1000P_0402_50V7K  [C_0402]  72.23 148.95 270 top
PCI51  1000P_0402_50V7K  [C_0402]  73.14 148.95 270 top
PCI52  1000P_0402_50V7K  [C_0402]  63.44 147.89 270 top
PCI53  1000P_0402_50V7K  [C_0402]  64.38 147.83 0 top
PCI101  10U_0402_6.3V6M  [C_0402]  93.1 115.3 0 top
PCI102  10U_0402_6.3V6M  [C_0402]  79.37 119.34 0 top
PCI103  10U_0402_6.3V6M  [C_0402]  93.1 116.25 0 top
PCI104  10U_0402_6.3V6M  [C_0402]  93 120.32 0 top
PCI105  10U_0402_6.3V6M  [C_0402]  93 119.37 0 top
PCI106  10U_0402_6.3V6M  [C_0402]  83.99 132.81 90 top
PCI107  10U_0402_6.3V6M  [C_0402]  93.09 114.37 0 top
PCI108  10U_0402_6.3V6M  [C_0402]  82.81 119.35 180 top
PCI109  10U_0402_6.3V6M  [C_0402]  82.8 120.28 180 top
PCI110  10U_0402_6.3V6M  [C_0402]  77.97 120.28 180 top
PCI111  10U_0402_6.3V6M  [C_0402]  77.97 119.33 180 top
PCI112  10U_0402_6.3V6M  [C_0402]  84.22 119.34 0 top
PCI113  10U_0402_6.3V6M  [C_0402]  93.1 117.2 0 top
PCI114  10U_0402_6.3V6M  [C_0402]  79.37 120.29 0 top
PCI115  10U_0402_6.3V6M  [C_0402]  91.74 119.34 180 top
PCI116  10U_0402_6.3V6M  [C_0402]  88.65 119.36 0 top
PCI117  10U_0402_6.3V6M  [C_0402]  87.37 119.3 180 top
PCI118  10U_0402_6.3V6M  [C_0402]  91.74 120.29 180 top
PCI119  10U_0402_6.3V6M  [C_0402]  88.65 120.31 0 top
PCI120  10U_0402_6.3V6M  [C_0402]  87.37 120.25 180 top
PCI121  10U_0402_6.3V6M  [C_0402]  84.22 120.27 0 top
PCI122  22U_0603_6.3V6M  [C_0603]  86.62 118.24 180 top
PCI123  22U_0603_6.3V6M  [C_0603]  87.64 118.25 0 top
PCI124  22U_0603_6.3V6M  [C_0603]  91.68 112.08 90 top
PCI125  22U_0603_6.3V6M  [C_0603]  81.44 112.17 180 top
PCI126  22U_0603_6.3V6M  [C_0603]  82.51 112.15 0 top
PCI127  22U_0603_6.3V6M  [C_0603]  90.37 112.08 90 top
PCI128  22U_0603_6.3V6M  [C_0603]  80.21 114.71 270 top
PCI129  22U_0603_6.3V6M  [C_0603]  92.51 118.29 0 top
PCI130  22U_0603_6.3V6M  [C_0603]  81.71 118.27 180 top
PCI131  22U_0603_6.3V6M  [C_0603]  82.8 118.25 0 top
PCI132  22U_0603_6.3V6M  [C_0603]  86.32 112.15 180 top
PCI133  22U_0603_6.3V6M  [C_0603]  91.52 118.29 180 top
PCI134  22U_0603_6.3V6M  [C_0603]  78.51 112.7 180 top
PCI135  22U_0603_6.3V6M  [C_0603]  88.74 112.17 180 top
PCI136  22U_0603_6.3V6M  [C_0603]  80.2 115.71 90 top
PCI137  47U_0805_6.3V6M  [C_0805]  92.08 114.98 180 top
PCI138  47U_0805_6.3V6M  [C_0805]  78.91 116.08 180 top
PCI139  47U_0805_6.3V6M  [C_0805]  92.07 116.75 180 top
PCI140  47U_0805_6.3V6M  [C_0805]  78.91 117.92 180 top
PCI141  47U_0805_6.3V6M  [C_0805]  78.91 114.27 180 top
PCI142  1U_0201_6.3V6M  [C_0201]  85.33 110.61 180 top
PCI143  1U_0201_6.3V6M  [C_0201]  85.31 111.18 180 top
PCI144  1U_0201_6.3V6M  [C_0201]  83.07 110.62 0 top
PCI145  1U_0201_6.3V6M  [C_0201]  89.74 111.2 0 top
PCI146  1U_0201_6.3V6M  [C_0201]  83.02 111.19 0 top
PCI147  1U_0201_6.3V6M  [C_0201]  93.17 110.59 0 top
PCI148  1U_0201_6.3V6M  [C_0201]  93.18 112.33 0 top
PCI149  1U_0201_6.3V6M  [C_0201]  78.44 111.26 180 top
PCI150  1U_0201_6.3V6M  [C_0201]  93.18 112.94 0 top
PCI151  1U_0201_6.3V6M  [C_0201]  93.18 113.53 0 top
PCI152  1U_0201_6.3V6M  [C_0201]  88.62 111.21 180 top
PCI153  1U_0201_6.3V6M  [C_0201]  86.46 111.18 0 top
PCI154  1U_0201_6.3V6M  [C_0201]  88.62 110.62 180 top
PCI155  1U_0201_6.3V6M  [C_0201]  79.59 111.23 0 top
PCI156  1U_0201_6.3V6M  [C_0201]  81.91 110.63 180 top
PCI157  1U_0201_6.3V6M  [C_0201]  92.03 111.19 180 top
PCI158  1U_0201_6.3V6M  [C_0201]  92.03 110.6 180 top
PCI159  1U_0201_6.3V6M  [C_0201]  81.91 111.23 180 top
PCI160  1U_0201_6.3V6M  [C_0201]  89.74 110.62 0 top
PCI161  1U_0201_6.3V6M  [C_0201]  86.46 110.61 0 top
PCI162  1U_0201_6.3V6M  [C_0201]  79.57 110.64 0 top
PCI163  1U_0201_6.3V6M  [C_0201]  93.17 111.17 0 top
PCI164  1U_0201_6.3V6M  [C_0201]  93.18 111.76 0 top
PCI165  1U_0201_6.3V6M  [C_0201]  78.44 110.69 180 top
PCI171  330U_X_2VM_R6M  [C_X]  76.85 133.13 0 bottom
PCI172  330U_X_2VM_R6M  [C_X]  73.52 133.13 180 bottom
PCI173  330U_X_2VM_R6M  [C_X]  82.59 115.21 0 top
PCM01  0.1U_0402_25V6  [C_0402]  41.42 48.79 0 top
PCM02  2200P_0402_50V7K  [C_0402]  41.42 49.68 0 top
PCM03  4.7U_0805_25V6K  [C_0805]  40.15 49 90 bottom
PCM04  4.7U_0805_25V6K  [C_0805]  40.15 49 90 top
PCM05  22U_0603_6.3V6M  [C_0603]  39.78 59.33 270 top
PCM06  22U_0603_6.3V6M  [C_0603]  34.01 62.04 180 bottom
PCM07  22U_0603_6.3V6M  [C_0603]  37.38 59.33 270 top
PCM08  22U_0603_6.3V6M  [C_0603]  34.01 60.81 180 bottom
PCM09  22U_0603_6.3V6M  [C_0603]  38.59 59.33 270 top
PCM10  22U_0603_6.3V6M  [C_0603]  40.99 59.33 270 top
PCM11  680P_0402_50V7K  [C_0402]  36.04 52.14 180 top
PCM12  0.1U_0402_10V7K  [C_0402]  35.46 46.65 270 bottom
PCM13  1U_0603_10V6K  [C_0603]  33.82 44.26 180 bottom
PCM14  1U_0603_10V6K  [C_0603]  33.82 40.59 180 bottom
PCM15  0.1U_0402_10V7K  [C_0402]  37.99 39.66 270 bottom
PCM16  0.1U_0402_10V7K  [C_0402]  38.88 39.66 270 bottom
PCM17  220P_0402_25V8J  [C_0402]  40.82 39.83 90 bottom
PCM18  .1U_0402_16V7K  [C_0402]  40.77 41.62 0 bottom
PCM19  0.033U_0402_16V7K  [C_0402]  40.77 42.57 0 bottom
PCM20  10U_0603_6.3V6M  [C_0603]  41.21 43.86 90 bottom
PCM21  10U_0603_6.3V6M  [C_0603]  41.21 43.86 90 top
PCM22  1000P_0402_50V7K  [C_0402]  41.42 48.79 0 bottom
PCM23  1000P_0402_50V7K  [C_0402]  41.42 49.68 0 bottom
PCS01  0.01U_0402_25V7K~D  [C_0402]  37.53 123.47 270 top
PCS02  100P_0402_50V8J~D  [C_0402]  32.13 129.78 90 top
PCS03  220P_0402_50V8J~D  [C_0402]  31.72 131.54 0 top
PCS04  1200P_0402_50V7K  [C_0402]  34.49 127.4 0 top
PCS05  100P_0402_50V8J  [C_0402]  19.98 63.74 180 top
PCS06  1000P_0402_50V7K  [C_0402]  19.98 62.83 180 top
PCS07  0.1U_0402_25V6  [C_0402]  20.71 61.92 180 top
PCS08  100P_0402_50V8J  [C_0402]  20.74 60.13 180 top
PCS09  0.47U_0603_25V7K  [C_0603]  19.15 55.65 270 bottom
PCS10  1500P_0402_50V7K  [C_0402]  25.51 44.26 270 bottom
PCS11  0.47U_0402_25V6K  [C_0402]  30.7 51.14 90 top
PCS12  0.1U_0402_10V7K  [C_0402]  20.36 41.22 90 top
PCS13  0.1U_0402_10V7K  [C_0402]  20.05 37.71 0 top
PCS14  0.1U_0402_10V7K  [C_0402]  22.78 37.71 180 top
PCS15  1000P_0603_50V7K  [C_0603]  35.46 69.29 270 top
PCS16  2.2U_0402_10V6M  [C_0402]  38.29 69.19 270 top
PCS19  .1U_0402_16V7K  [C_0402]  23.25 112.93 180 top
PCS20  .1U_0402_16V7K  [C_0402]  23.25 112.01 180 top
PCS21  1500P_0402_50V7K  [C_0402]  27.25 54.97 0 bottom
PCS22  0.1U_0402_10V7K  [C_0402]  32.79 59.84 270 top
PCS23  4.7U_0603_25V6K  [C_0603]  20.18 52.59 180 bottom
PCV01  1U_0603_16V7  [C_0603]  255.34 66.6 0 bottom
PCV02  1000P_0402_50V7K  [C_0402]  254.58 68.61 270 bottom
PCV03  4700P_0402_50V7K  [C_0402]  252.86 59.38 0 bottom
PCV04  47P_0402_50V8J  [C_0402]  254.81 70.83 270 bottom
PCV05  330P_0402_50V8J  [C_0402]  253.05 71.71 0 bottom
PCV06  4700P_0402_50V7K  [C_0402]  255.63 62.1 180 bottom
PCV07  2200P_0402_25V7K  [C_0402]  255.71 70.83 270 bottom
PCV08  0.01U_0402_16V7K  [C_0402]  252.88 60.32 90 bottom
PCV09  0.01U_0402_50V7K  [C_0402]  251.99 61.24 270 bottom
PCV10  1000P_0402_25V8J  [C_0402]  249.58 70.86 90 bottom
PCV11  0.1U_0402_25V7K  [C_0402]  246.79 71.78 270 bottom
PCV12  560P_0402_50V7K  [C_0402]  249.4 68.78 180 top
PCV13  680P_0402_50V7K  [C_0402]  249.4 70.31 180 top
PCV14  0.068U_0402_16V7K  [C_0402]  245.85 70.86 180 bottom
PCV15  0.068U_0402_16V7K  [C_0402]  245.96 68.96 270 bottom
PCV16  0.068U_0402_16V7K  [C_0402]  245.06 66.16 90 bottom
PCV17  1000P_0402_50V7K  [C_0402]  211.63 63.63 180 top
PCV18  1000P_0402_50V7K  [C_0402]  211.63 62.7 180 top
PCV19  2200P_0402_50V7K  [C_0402]  211.63 63.63 180 bottom
PCV20  0.1U_0402_25V7K  [C_0402]  211.63 62.71 180 bottom
PCV21  10U_0805_25VAK  [C_0805]  212.02 66.77 180 bottom
PCV22  10U_0805_25VAK  [C_0805]  212 66.74 180 top
PCV23  10U_0805_25VAK  [C_0805]  212.01 65 180 bottom
PCV24  10U_0805_25VAK  [C_0805]  211.99 64.99 180 top
PCV26  1U_0603_25V7K  [C_0603]  216.44 63.01 90 bottom
PCV27  0.22U_0603_25V7K  [C_0603]  214 62.95 90 bottom
PCV28  2.2U_0603_10V7K  [C_0603]  218.91 62.95 90 bottom
PCV29  680P_0603_50V7K  [C_0603]  218.09 70.67 90 top
PCV30  2200P_0402_50V7K  [C_0402]  221.49 63.03 180 bottom
PCV31  0.1U_0402_25V7K  [C_0402]  221.49 63.94 180 bottom
PCV32  10U_0805_25VAK  [C_0805]  221.99 67.06 180 bottom
PCV33  10U_0805_25VAK  [C_0805]  221.97 67.07 180 top
PCV34  10U_0805_25VAK  [C_0805]  221.97 65.27 180 top
PCV35  10U_0805_25VAK  [C_0805]  221.99 65.27 180 bottom
PCV36  1U_0603_25V7K  [C_0603]  226.54 62.81 90 bottom
PCV37  0.22U_0603_25V7K  [C_0603]  224.14 62.82 90 bottom
PCV38  2.2U_0603_10V7K  [C_0603]  228.95 62.83 90 bottom
PCV39  680P_0603_50V7K  [C_0603]  223.78 70.76 90 top
PCV40  2200P_0402_50V7K  [C_0402]  231.6 63.83 180 bottom
PCV41  0.1U_0402_25V7K  [C_0402]  231.58 62.9 180 bottom
PCV42  10U_0805_25VAK  [C_0805]  232.1 66.94 180 bottom
PCV43  10U_0805_25VAK  [C_0805]  232.1 66.93 180 top
PCV44  10U_0805_25VAK  [C_0805]  232.1 65.17 180 top
PCV45  10U_0805_25VAK  [C_0805]  232.13 65.15 180 bottom
PCV46  1U_0603_25V7K  [C_0603]  236.58 62.94 90 bottom
PCV47  0.22U_0603_25V7K  [C_0603]  234.14 62.95 90 bottom
PCV48  2.2U_0603_10V7K  [C_0603]  239 62.92 90 bottom
PCV49  680P_0603_50V7K  [C_0603]  233.66 70.66 90 top
PCV50  100U_25V_M  [C_ECST250ADA101MF611]  222.13 57.72 180 bottom
PCV54  1000P_0402_50V7K  [C_0402]  221.48 63.05 180 top
PCV55  1000P_0402_50V7K  [C_0402]  221.48 63.95 180 top
PCV56  1000P_0402_50V7K  [C_0402]  231.58 63.82 180 top
PCV57  1000P_0402_50V7K  [C_0402]  231.57 62.91 180 top
PCV101  1U_0402_6.3V6K  [C_0402]  218.62 106.95 270 top
PCV102  1U_0402_6.3V6K  [C_0402]  219.99 101.15 0 top
PCV103  1U_0402_6.3V6K  [C_0402]  223.5 102.09 90 top
PCV104  1U_0402_6.3V6K  [C_0402]  219.54 103.05 0 top
PCV105  1U_0402_6.3V6K  [C_0402]  220.46 109.05 180 top
PCV106  1U_0402_6.3V6K  [C_0402]  215.5 107.09 90 top
PCV107  1U_0402_6.3V6K  [C_0402]  215.6 113.02 270 top
PCV108  1U_0402_6.3V6K  [C_0402]  224.5 113.01 270 top
PCV109  4.7U_0603_6.3V6K  [C_0603]  216.8 98.08 180 top
PCV110  4.7U_0603_6.3V6K  [C_0603]  216.8 99.28 180 top
PCV111  4.7U_0603_6.3V6K  [C_0603]  235.76 76.01 270 top
PCV112  4.7U_0603_6.3V6K  [C_0603]  236.96 76.01 270 top
PCV113  4.7U_0603_6.3V6K  [C_0603]  215.58 102.68 0 top
PCV114  4.7U_0603_6.3V6K  [C_0603]  218.55 101.33 180 top
PCV115  4.7U_0603_6.3V6K  [C_0603]  219.6 100.1 0 top
PCV116  4.7U_0603_6.3V6K  [C_0603]  219.6 98.5 0 top
PCV117  4.7U_0603_6.3V6K  [C_0603]  218.37 99.88 270 top
PCV118  4.7U_0603_6.3V6K  [C_0603]  219 111.85 90 top
PCV119  4.7U_0603_6.3V6K  [C_0603]  219.52 74.51 270 top
PCV120  4.7U_0603_6.3V6K  [C_0603]  218.25 74.5 270 top
PCV121  4.7U_0603_6.3V6K  [C_0603]  216.99 74.45 270 top
PCV122  4.7U_0603_6.3V6K  [C_0603]  220.81 74.52 270 top
PCV123  4.7U_0603_6.3V6K  [C_0603]  223.34 74.51 270 top
PCV124  4.7U_0603_6.3V6K  [C_0603]  222.08 74.52 270 top
PCV125  10U_0603_6.3V6M  [C_0603]  222.26 101.5 90 top
PCV126  10U_0603_6.3V6M  [C_0603]  224.8 101.85 90 top
PCV127  10U_0603_6.3V6M  [C_0603]  217.15 105.74 270 top
PCV128  10U_0603_6.3V6M  [C_0603]  219.3 104.48 0 top
PCV129  10U_0603_6.3V6M  [C_0603]  224.8 107.4 90 top
PCV130  10U_0603_6.3V6M  [C_0603]  223 108.35 90 top
PCV131  10U_0603_6.3V6M  [C_0603]  217 109.75 270 top
PCV132  10U_0603_6.3V6M  [C_0603]  220.7 110.35 180 top
PCV133  10U_0603_6.3V6M  [C_0603]  221 111.85 90 top
PCV134  22U_0805_6.3VAM  [C_0805]  218.05 94.93 0 top
PCV135  22U_0805_6.3VAM  [C_0805]  220.96 83.87 90 bottom
PCV136  22U_0805_6.3VAM  [C_0805]  218.03 89.76 0 top
PCV137  22U_0805_6.3VAM  [C_0805]  218.03 91.49 0 top
PCV138  22U_0805_6.3VAM  [C_0805]  218.04 93.21 0 top
PCV139  22U_0805_6.3VAM  [C_0805]  222.9 83.88 90 bottom
PCV140  22U_0805_6.3VAM  [C_0805]  224.84 83.87 90 bottom
PCV171  470U_D2_2VM_R4.5M~D  [C_D1]  218.29 83.91 180 bottom
PCV172  470U_D2_2VM_R4.5M~D  [C_D1]  214.99 76.51 180 top
PCV173  330U_X_2VM_R6M  [C_X]  215.36 92.23 180 top
PCV201  1U_0402_6.3V6K  [C_0402]  223.2 111.19 180 top
PCV202  1U_0402_6.3V6K  [C_0402]  223.07 112.97 270 top
PCV203  1U_0402_6.3V6K  [C_0402]  215.6 111.06 270 top
PCV204  1U_0402_6.3V6K  [C_0402]  224.52 111.04 270 top
PCV205  1U_0402_6.3V6K  [C_0402]  224.54 106.03 270 top
PCV206  10U_0603_6.3V6M  [C_0603]  229.64 74.55 270 top
PCV207  10U_0603_6.3V6M  [C_0603]  232.18 74.56 270 top
PCV208  22U_0805_6.3VAM  [C_0805]  228.7 83.89 90 bottom
PCV209  22U_0805_6.3VAM  [C_0805]  226.79 83.88 90 bottom
PCV210  22U_0805_6.3VAM  [C_0805]  230.62 83.88 90 bottom
PCV211  10U_0603_6.3V6M  [C_0603]  228.37 74.54 270 top
PCV212  10U_0603_6.3V6M  [C_0603]  238.18 76 270 top
PCV213  10U_0603_6.3V6M  [C_0603]  230.91 74.56 270 top
PCV214  10U_0603_6.3V6M  [C_0603]  223 104.35 90 top
PCV215  10U_0603_6.3V6M  [C_0603]  215.83 105.76 270 top
PCV216  4.7U_0603_6.3V6K  [C_0603]  217 112.75 270 top
PCV217  4.7U_0603_6.3V6K  [C_0603]  220.91 107.82 270 top
PCV271  470U_D2_2VM_R4.5M~D  [C_D1]  241.25 79.56 270 bottom
PCV272  330U_X_2VM_R6M  [C_X]  233.53 84 0 bottom
PCW01  2200P_0402_50V7K  [C_0402]  265.71 76.38 90 bottom
PCW02  0.1U_0402_25V7K  [C_0402]  264.44 76.38 90 bottom
PCW03  10U_0805_25VAK  [C_0805]  267.06 75.95 90 bottom
PCW04  10U_0805_25VAK  [C_0805]  267.06 75.98 90 top
PCW05  10U_0805_25VAK  [C_0805]  263.81 76.03 180 top
PCW06  10U_0805_25VAK  [C_0805]  265.27 75.97 90 top
PCW07  1000P_0402_50V7K  [C_0402]  263.63 74.71 180 top
PCW08  1000P_0402_50V7K  [C_0402]  263.64 73.78 180 top
PCW09  2.2U_0603_10V7K  [C_0603]  261.4 66.09 180 bottom
PCW10  0.1U_0402_25V7K  [C_0402]  267.83 66.51 0 bottom
PCW11  0.22U_0603_25V7K  [C_0603]  261.12 69.19 90 bottom
PCW12  680P_0402_50V7K  [C_0402]  263.34 79.24 0 bottom
PCW13  0.1U_0402_25V7K  [C_0402]  265.96 71.25 90 top
PCW14  0.1U_0402_25V7K  [C_0402]  266.46 66.79 90 top
PCW15  2700P_0402_50V7K  [C_0402]  267.84 70.76 0 bottom
PCW17  47P_0402_50V8J  [C_0402]  265.3 65.05 270 bottom
PCW18  220U_D2 SX_2VY_R9M  [C_D2]  258.52 88.1 0 bottom
PCW19  220U_D2 SX_2VY_R9M  [C_D2]  254.42 88.07 180 bottom
PCZ01  2200P_0402_50V7K  [C_0402]  106.34 141.38 90 top
PCZ02  1000P_0402_50V7K  [C_0402]  103.68 141.4 90 top
PCZ03  1000P_0402_50V7K  [C_0402]  104.6 141.4 90 top
PCZ04  1000P_0402_50V7K  [C_0402]  101.91 143.33 0 bottom
PCZ05  2200P_0402_50V7K  [C_0402]  101.77 144.16 0 top
PCZ06  0.01UF_0402_25V7K  [C_0402]  107.26 142.13 0 bottom
PCZ07  2200P_0402_50V7K  [C_0402]  107.26 141.2 0 bottom
PCZ08  470P_0402_50V8J  [C_0402]  107.97 144.81 270 top
PCZ09  1000P_0402_50V7K  [C_0402]  105.23 144.77 270 top
PCZ10  0.01U_0402_25V7K  [C_0402]  106.4 142.35 180 bottom
PCZ11  100P_0402_50V8J  [C_0402]  106.37 140.57 90 bottom
PCZ12  10U_0402_6.3V6M  [C_0402]  112.07 141.37 90 top
PCZ13  15P_0402_50V8J  [C_0402]  101.94 146.93 270 bottom
PCZ14  470P_0402_50V8J  [C_0402]  101.77 145.08 0 top
PCZ15  2200P_0402_50V7K  [C_0402]  101.02 146.93 270 bottom
PCZ16  470P_0402_50V8J  [C_0402]  104.41 146.97 0 top
PCZ17  100P_0402_50V8J  [C_0402]  101.79 146.76 90 top
PCZ18  680P_0402_50V7K  [C_0402]  102.72 147.67 270 top
PCZ19  0.22U_0402_25V6K  [C_0402]  105.93 148.34 180 top
PCZ20  1000P_0402_50V7K  [C_0402]  112.78 145.56 0 top
PCZ21  2200P_0402_50V7K  [C_0402]  112.83 144.69 0 bottom
PCZ22  470P_0402_50V8J  [C_0402]  110.44 146.91 180 top
PCZ23  470P_0402_50V8J  [C_0402]  114.55 147.26 180 bottom
PCZ24  15P_0402_50V8J  [C_0402]  112.82 146.45 90 top
PCZ25  2200P_0402_50V7K  [C_0402]  114.6 147.27 180 top
PCZ26  0.22U_0402_25V6K  [C_0402]  110.95 148.94 180 top
PCZ27  100P_0402_50V8J  [C_0402]  113.65 149.09 180 top
PCZ28  680P_0402_50V7K  [C_0402]  113.67 148.17 90 bottom
PCZ29  0.1U_0402_25V6  [C_0402]  104.39 152.38 90 bottom
PCZ30  0.01U_0402_50V7K  [C_0402]  105.32 153.31 270 bottom
PCZ31  0.1U_0402_25V6  [C_0402]  109.87 152.63 90 bottom
PCZ32  1U_0603_10V6K  [C_0603]  106.38 152.53 90 bottom
PCZ33  0.1U_0402_25V6  [C_0402]  111.63 150.82 0 top
PCZ34  0.1U_0402_25V6  [C_0402]  104.99 149.26 180 top
PCZ35  0.1U_0402_25V6  [C_0402]  104.99 150.15 180 top
PCZ36  0.1U_0402_25V6  [C_0402]  104.99 151.04 180 top
PCZ37  0.1U_0402_25V6  [C_0402]  112.43 152.41 180 bottom
PCZ38  3300P_0402_25V7K  [C_0402]  107.08 143.95 90 top
PD1  -  [TVNST52302AB0_SOT523-3]  42.49 142.76 90 top
PD2  -  [BAV99W_SC70-3]  48.92 140.47 270 top
PD3  -  [BAV99W_SC70-3]  45.33 137.98 90 top
PD4  S SCH DIO 5A 100V 15UA 0.88V TO227-3  [PDS5100H-13_POWERDI5-3]  36.07 111.32 90 bottom
PD5  -  [TVNST52302AB0_SOT523-3]  209.23 38.33 90 top
PD6  -  [TVNST52302AB0_SOT523-3]  212.84 37.46 0 top
